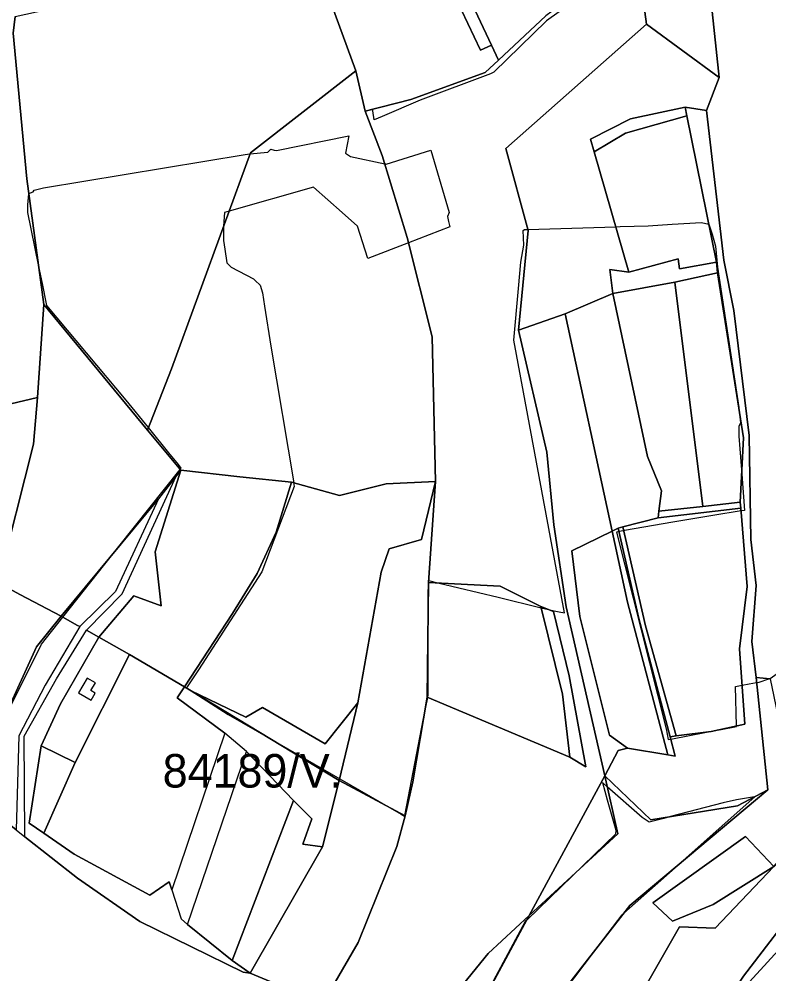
# Model space of a CAD drawing. Extents: x -477304 to -465429, y -1159113 to -1149210.
# Drawn here: x -472117.1 to -471781.8, y -1154340.7 to -1153913.5 of the extents above; entities that cross this region are included whole.
import ezdxf

# ---------------------------------------------------------------- set-up
doc = ezdxf.new("R2010")
doc.units = 0
for name, color, linetype in [('BPEJ_s', 7, 'Continuous'), ('PUPFL_s', 7, 'Continuous'), ('trav_porost_s', 7, 'Continuous'), ('zahrada_s', 7, 'Continuous')]:
    doc.layers.add(name, color=color, linetype=linetype)

msp = doc.modelspace()

# ---------------------------------------------------------------- linework, layer by layer
at = {"layer": 'BPEJ_s'}
for points in [[(-471858.64, -1153897.99), (-471881.28, -1153914.36), (-471904.87, -1153937.31), (-471906.36, -1153937.95), (-471937.82, -1153949.85), (-471954.82, -1153957.08), (-471958.28, -1153958.55), (-471958.86, -1153954.53), (-471958.96, -1153953.79), (-471962.4, -1153954.64), (-471966.51, -1153936.68), (-471979.78, -1153900.24)], [(-471858.64, -1153897.99), (-471881.28, -1153914.36), (-471904.87, -1153937.31), (-471906.36, -1153937.95), (-471937.82, -1153949.85), (-471954.82, -1153957.08), (-471958.28, -1153958.55), (-471958.86, -1153954.53), (-471958.96, -1153953.79), (-471962.4, -1153954.64), (-471966.51, -1153936.68), (-471979.78, -1153900.24)], [(-472126.75, -1154232.46), (-472107.09, -1154193.16), (-472097.54, -1154181.12), (-472072.46, -1154149.52), (-472045.06, -1154114.98), (-472044.62, -1154114.42), (-472045.9, -1154112.84), (-472050.19, -1154107.53), (-472059.27, -1154096.3), (-472069.27, -1154083.94), (-472104.75, -1154041.66), (-472106.75, -1154031.87), (-472108.45, -1154023.53), (-472113.24, -1154000), (-472113.17, -1153996.61), (-472112.76, -1153991.72), (-472112.76, -1153991.63), (-472112.75, -1153991.51), (-472110.83, -1153990.87), (-472110.41, -1153990.02), (-472106.16, -1153988.96), (-472016.03, -1153974.08), (-472013.9, -1153973.86), (-472005.83, -1153973.02), (-472004.56, -1153971.75), (-472003.05, -1153972.12), (-472002.01, -1153972.38), (-471969.66, -1153965.71), (-471971.18, -1153973.45), (-471968.85, -1153974.93), (-471953.61, -1153978.21), (-471953.3, -1153978.28), (-471952.9, -1153978.37), (-471932.93, -1153972.14), (-471924.85, -1154000), (-471925.54, -1154001.87), (-471925.04, -1154004), (-471924.46, -1154006.51), (-471942.98, -1154013.65), (-471961.11, -1154020.64), (-471965.76, -1154006.16), (-471972.63, -1154000), (-471985.42, -1153988.71), (-472023.22, -1153999.4), (-472025.33, -1154000), (-472025.71, -1154006.2), (-472025.71, -1154012.55), (-472025.13, -1154016.5), (-472024.23, -1154022.54), (-472022.31, -1154024.45), (-472012.33, -1154029.76), (-472011.53, -1154030.5), (-472009.35, -1154032.52), (-472008.29, -1154035.92), (-472007.33, -1154042), (-472004.52, -1154059.81), (-471994.33, -1154120.97), (-471994.21, -1154121.69), (-471994.05, -1154122.61), (-472008.5, -1154160.86), (-472036.97, -1154204.63), (-472042.28, -1154212.78), (-472023.59, -1154224.6), (-472004.72, -1154235.49), (-471973.74, -1154253.36), (-471951.23, -1154266.35), (-471946.24, -1154269.22), (-471944.69, -1154270.12), (-471944.65, -1154269.9), (-471936.21, -1154226.36), (-471934.38, -1154216.96), (-471934.13, -1154215.68), (-471934.13, -1154179.18), (-471934.13, -1154169.78), (-471933.99, -1154167.43), (-471933.88, -1154165.62), (-471933.83, -1154164.76), (-471929.29, -1154165.85)], [(-472069.27, -1154083.94), (-472104.75, -1154041.66), (-472106.75, -1154031.87), (-472108.45, -1154023.53), (-472113.24, -1154000), (-472113.17, -1153996.61), (-472112.76, -1153991.72), (-472112.76, -1153991.63), (-472112.75, -1153991.51), (-472110.83, -1153990.87), (-472110.41, -1153990.02), (-472106.16, -1153988.96), (-472016.03, -1153974.08), (-472013.9, -1153973.86), (-472005.83, -1153973.02), (-472004.56, -1153971.75), (-472003.05, -1153972.12), (-472002.01, -1153972.38), (-471969.66, -1153965.71), (-471971.18, -1153973.45), (-471968.85, -1153974.93), (-471953.61, -1153978.21), (-471953.3, -1153978.28), (-471952.9, -1153978.37), (-471932.93, -1153972.14), (-471924.85, -1154000), (-471925.54, -1154001.87), (-471925.04, -1154004), (-471924.46, -1154006.51), (-471942.98, -1154013.65), (-471961.11, -1154020.64), (-471965.76, -1154006.16), (-471972.63, -1154000), (-471985.42, -1153988.71), (-472023.22, -1153999.4), (-472025.33, -1154000), (-472025.71, -1154006.2), (-472025.71, -1154012.55), (-472025.13, -1154016.5), (-472024.23, -1154022.54), (-472022.31, -1154024.45), (-472012.33, -1154029.76), (-472011.53, -1154030.5), (-472009.35, -1154032.52), (-472008.29, -1154035.92), (-472007.33, -1154042), (-472004.52, -1154059.81), (-471994.33, -1154120.97), (-471994.21, -1154121.69), (-471994.05, -1154122.61), (-472008.5, -1154160.86), (-472036.97, -1154204.63), (-472042.28, -1154212.78), (-472023.59, -1154224.6), (-472004.72, -1154235.49), (-471973.74, -1154253.36), (-471951.23, -1154266.35), (-471946.24, -1154269.22), (-471944.69, -1154270.12), (-471944.65, -1154269.9), (-471936.21, -1154226.36), (-471934.38, -1154216.96), (-471934.13, -1154215.68), (-471934.13, -1154179.18), (-471934.13, -1154169.78), (-471933.99, -1154167.43), (-471933.88, -1154165.62), (-471933.83, -1154164.76), (-471929.29, -1154165.85), (-471902.91, -1154172.17), (-471883.62, -1154176.87), (-471880.4, -1154177.66), (-471877.83, -1154178.28), (-471875.63, -1154178.71), (-471873.17, -1154179.2), (-471895.89, -1154057.17), (-471893.77, -1154034.06), (-471892.7, -1154022.32), (-471891.42, -1154014.67), (-471891.64, -1154008.09), (-471891.01, -1154007.66), (-471889.53, -1154007.62), (-471850.27, -1154006.41), (-471848.31, -1154006.35), (-471835.76, -1154005.96), (-471825.02, -1154005.29), (-471811.96, -1154004.48), (-471808.65, -1154005.3), (-471808.56, -1154005.33), (-471807.2, -1154009.78), (-471805.58, -1154015.1), (-471804.73, -1154024.45), (-471795.17, -1154087.34), (-471795.15, -1154087.58), (-471794.53, -1154094.14), (-471795.17, -1154095.84), (-471795.17, -1154100.09), (-471793.92, -1154117.15), (-471792.74, -1154133.3), (-471794.21, -1154133.54), (-471806.89, -1154135.59)], [(-471929.29, -1154165.85), (-471902.91, -1154172.17), (-471883.62, -1154176.87), (-471880.4, -1154177.66), (-471877.83, -1154178.28), (-471875.63, -1154178.71), (-471873.17, -1154179.2), (-471895.89, -1154057.17), (-471893.77, -1154034.06), (-471892.7, -1154022.32), (-471891.42, -1154014.67), (-471891.64, -1154008.09), (-471891.01, -1154007.66), (-471889.53, -1154007.62), (-471850.27, -1154006.41), (-471848.31, -1154006.35), (-471835.76, -1154005.96), (-471825.02, -1154005.29), (-471811.96, -1154004.48), (-471808.65, -1154005.3), (-471808.56, -1154005.33), (-471807.2, -1154009.78), (-471805.58, -1154015.1), (-471804.73, -1154024.45), (-471795.17, -1154087.34), (-471795.15, -1154087.58), (-471794.53, -1154094.14), (-471795.17, -1154095.84), (-471795.17, -1154100.09), (-471793.92, -1154117.15), (-471792.74, -1154133.3), (-471794.21, -1154133.54), (-471806.89, -1154135.59), (-471824.79, -1154138.66), (-471846.38, -1154142.37), (-471846.55, -1154142.4), (-471846.73, -1154142.44), (-471848.84, -1154142.8), (-471850, -1154143), (-471827.68, -1154230.98), (-471826.86, -1154235.85), (-471825.69, -1154235.63), (-471809.62, -1154232.54), (-471806.51, -1154231.95), (-471803.07, -1154231.29), (-471796.19, -1154229.97), (-471796.2, -1154229.76), (-471796.68, -1154212.06), (-471793.77, -1154211.54), (-471790.64, -1154210.98), (-471787.26, -1154210.37), (-471786.04, -1154210.15), (-471781.79, -1154208.67), (-471781.7, -1154208.61)], [(-472126.75, -1154232.46), (-472107.09, -1154193.16), (-472097.54, -1154181.12), (-472072.46, -1154149.52), (-472045.06, -1154114.98), (-472044.62, -1154114.42), (-472045.9, -1154112.84), (-472050.19, -1154107.53), (-472059.27, -1154096.3), (-472069.27, -1154083.94)], [(-471806.89, -1154135.59), (-471824.79, -1154138.66), (-471846.38, -1154142.37), (-471846.55, -1154142.4), (-471846.73, -1154142.44), (-471848.84, -1154142.8), (-471850, -1154143), (-471827.68, -1154230.98), (-471826.86, -1154235.85), (-471825.69, -1154235.63), (-471809.62, -1154232.54), (-471806.51, -1154231.95), (-471803.07, -1154231.29), (-471796.19, -1154229.97), (-471796.2, -1154229.76), (-471796.68, -1154212.06), (-471793.77, -1154211.54), (-471790.64, -1154210.98), (-471787.26, -1154210.37), (-471786.04, -1154210.15), (-471781.79, -1154208.67), (-471781.7, -1154208.61)], [(-471912.04, -1154399.69), (-471855.58, -1154325.03), (-471847.44, -1154314.27), (-471846.65, -1154313.57), (-471821.16, -1154290.97), (-471820.19, -1154290.11), (-471787.83, -1154261.35), (-471788.13, -1154261.41), (-471796.24, -1154262.85), (-471802.18, -1154264.12), (-471825.76, -1154270.32), (-471828.78, -1154271.12), (-471835.33, -1154272.84), (-471838.52, -1154270.71), (-471854.05, -1154257.02), (-471856.2, -1154255.13), (-471854.03, -1154262.85), (-471850.2, -1154276.45), (-471850.42, -1154278.15), (-471869.64, -1154296.77), (-471889.96, -1154316.44), (-471890.79, -1154317.24), (-471935.82, -1154401.22)], [(-471912.04, -1154399.69), (-471855.58, -1154325.03), (-471847.44, -1154314.27), (-471846.65, -1154313.57), (-471821.16, -1154290.97), (-471820.19, -1154290.11), (-471787.83, -1154261.35), (-471788.13, -1154261.41), (-471796.24, -1154262.85), (-471802.18, -1154264.12), (-471825.76, -1154270.32), (-471828.78, -1154271.12), (-471835.33, -1154272.84), (-471838.52, -1154270.71), (-471854.05, -1154257.02), (-471856.2, -1154255.13), (-471854.03, -1154262.85), (-471850.2, -1154276.45), (-471850.42, -1154278.15), (-471869.64, -1154296.77), (-471889.96, -1154316.44), (-471890.79, -1154317.24), (-471935.82, -1154401.22)]]:
    msp.add_lwpolyline(points, dxfattribs=at)
at = {"layer": 'PUPFL_s'}
for points in [[(-471841.61, -1153878.07), (-471836.46, -1153915.86), (-471899.42, -1153971.4), (-471889.38, -1154008.16), (-471893.74, -1154052.75), (-471881.11, -1154107.33), (-471877.89, -1154139.79), (-471872.5, -1154176.44), (-471855.2, -1154252.01), (-471888.96, -1154314.59), (-471907.31, -1154331.52), (-471955.98, -1154391.34)], [(-471809.55, -1153887.46), (-471803.96, -1153939.59), (-471836.46, -1153915.86), (-471841.61, -1153878.07)], [(-471734.4, -1153905.75), (-471726.4, -1153959.93), (-471710.55, -1154003.53), (-471701.77, -1154028.61), (-471695.67, -1154044.05), (-471690.13, -1154061.98), (-471696.38, -1154070.81), (-471710.32, -1154086.43), (-471737.71, -1154129.54), (-471723.95, -1154151.12), (-471712.78, -1154176.98), (-471754.14, -1154191.03), (-471771.35, -1154201.7), (-471781.26, -1154208.65), (-471787.5, -1154208.08), (-471789.38, -1154191.93), (-471787.42, -1154166.99), (-471789.78, -1154146.28), (-471790.63, -1154099.78), (-471797.5, -1154043.85), (-471801.99, -1154021.33), (-471809.71, -1153954.36), (-471803.96, -1153939.59), (-471809.55, -1153887.46)], [(-472118.97, -1153912.3), (-472119.87, -1153919.78), (-472113.67, -1153985.03), (-472106.04, -1154041.27), (-472108.95, -1154082.78), (-472129.86, -1154087.81), (-472136.92, -1154051.38), (-472147.07, -1154009), (-472146.25, -1153978.67), (-472156.34, -1153957.61), (-472152.92, -1153942.04), (-472154.92, -1153925.34), (-472163.81, -1153915.07), (-472155.6, -1153912.17)], [(-471981.07, -1154353.65), (-471965.54, -1154326.58), (-471948.2, -1154283.67), (-471944.42, -1154270.02), (-471941.04, -1154254.76), (-471934.59, -1154216.87), (-471870.83, -1154243.66), (-471863.68, -1154248.06), (-471871.04, -1154207.41), (-471878.08, -1154178.62), (-471883.77, -1154176.26), (-471901.98, -1154167.18), (-471933.97, -1154165.62), (-471930.91, -1154120.34), (-471932.43, -1154055.71), (-471943.58, -1154011.28), (-471954.71, -1153974.57), (-471962.4, -1153954.64), (-471941.9, -1153949.55), (-471908.66, -1153937.46), (-471902.71, -1153931.9), (-471881.47, -1153912.02)], [(-472129.86, -1154087.81), (-472108.95, -1154082.78), (-472110.64, -1154103.7), (-472126.56, -1154165.78)], [(-471578.76, -1154463.85), (-471583.86, -1154490.96), (-471670.21, -1154492.33), (-471695.35, -1154463.3), (-471659.44, -1154426.99), (-471716.96, -1154340.3), (-471781.56, -1154355.08), (-471818.22, -1154378.77), (-471793.13, -1154341.75), (-471766.09, -1154306.48), (-471741.12, -1154276.97), (-471668.47, -1154252.77), (-471645.63, -1154265.51), (-471636.59, -1154269.05), (-471626.65, -1154273.16), (-471608.33, -1154269.66), (-471583.68, -1154248.83), (-471581.21, -1154243.16), (-471580.06, -1154226.43)]]:
    msp.add_lwpolyline(points, dxfattribs=at)
for points in [[(-472033.56, -1153904.42), (-472003.39, -1153894.1), (-471986.27, -1153882.43), (-471979.78, -1153900.24), (-471966.51, -1153936.68), (-472013.69, -1153973.29), (-472049, -1154070.03), (-472059.7, -1154097.39), (-472106.04, -1154041.27), (-472113.67, -1153985.03), (-472119.87, -1153919.78), (-472118.97, -1153912.3), (-472104.61, -1153909.28), (-472069.45, -1153902.97), (-472065.82, -1153902.95), (-472062.72, -1153902.93), (-472062.48, -1153907.01)], [(-471893.74, -1154052.75), (-471889.38, -1154008.16), (-471899.42, -1153971.4), (-471836.46, -1153915.86), (-471803.96, -1153939.59), (-471809.71, -1153954.36), (-471819.22, -1153952.9), (-471843.66, -1153958.17), (-471861.6, -1153967.31), (-471859.96, -1153972.97), (-471844.37, -1154026.79), (-471852.88, -1154025.58), (-471851.54, -1154036.22), (-471872.92, -1154045.39)], [(-471966.51, -1153936.68), (-471962.4, -1153954.64), (-471954.71, -1153974.57), (-471943.58, -1154011.28), (-471932.43, -1154055.71), (-471930.91, -1154120.34), (-471952.91, -1154121.48), (-471973.86, -1154126.7), (-471995.3, -1154120.7), (-472018.39, -1154118.27), (-472044.74, -1154115.37), (-472059.7, -1154097.39), (-472049, -1154070.03), (-472013.69, -1153973.29)], [(-471819.22, -1153952.9), (-471818.43, -1153956.82), (-471845.96, -1153964.51), (-471859.96, -1153972.97), (-471861.6, -1153967.31), (-471843.66, -1153958.17)], [(-471849.15, -1154240.79), (-471844.95, -1154239.68), (-471827.01, -1154242.67), (-471823.69, -1154243.22), (-471825.96, -1154234.59), (-471823.27, -1154234.25), (-471807.59, -1154232.29), (-471792.55, -1154228.95), (-471794.9, -1154195.31), (-471791.45, -1154167.34), (-471794.31, -1154132.34), (-471794.58, -1154129.64), (-471793.06, -1154100.8), (-471804.72, -1154027.04), (-471805.25, -1154022.24), (-471818.43, -1153956.82), (-471819.22, -1153952.9), (-471809.71, -1153954.36), (-471801.99, -1154021.33), (-471797.5, -1154043.85), (-471790.63, -1154099.78), (-471789.78, -1154146.28), (-471787.42, -1154166.99), (-471789.38, -1154191.93), (-471787.5, -1154208.08), (-471782.26, -1154258.3), (-471795.82, -1154265.47), (-471834.64, -1154271.76), (-471855.2, -1154252.01)], [(-471859.96, -1153972.97), (-471845.96, -1153964.51), (-471818.43, -1153956.82), (-471805.25, -1154022.24), (-471821.76, -1154025.21), (-471822.4, -1154020.77), (-471844.37, -1154026.79)], [(-471822.4, -1154020.77), (-471821.76, -1154025.21), (-471805.25, -1154022.24), (-471804.72, -1154027.04), (-471823.88, -1154031.15), (-471851.54, -1154036.22), (-471852.88, -1154025.58), (-471844.37, -1154026.79)], [(-471794.58, -1154129.64), (-471811.3, -1154131.55), (-471823.88, -1154031.15), (-471804.72, -1154027.04), (-471793.06, -1154100.8)], [(-471829.79, -1154124.58), (-471836.02, -1154109.24), (-471851.54, -1154036.22), (-471823.88, -1154031.15), (-471811.3, -1154131.55), (-471830.97, -1154133.67)], [(-471849.19, -1154141.26), (-471851.92, -1154142.59), (-471872.92, -1154045.39), (-471851.54, -1154036.22), (-471836.02, -1154109.24), (-471829.79, -1154124.58), (-471830.97, -1154133.67), (-471831.36, -1154136.63), (-471847.13, -1154140.72)], [(-472110.64, -1154103.7), (-472108.95, -1154082.78), (-472106.04, -1154041.27), (-472059.7, -1154097.39), (-472044.74, -1154115.37), (-472046.86, -1154118.07), (-472054.75, -1154128.13), (-472098.29, -1154180.7), (-472116.8, -1154170.98), (-472126.56, -1154165.78)], [(-471872.92, -1154045.39), (-471851.92, -1154142.59), (-471869.94, -1154151.37), (-471866.4, -1154180.86), (-471853.02, -1154233.87), (-471844.95, -1154239.68), (-471849.15, -1154240.79), (-471855.2, -1154252.01), (-471872.5, -1154176.44), (-471877.89, -1154139.79), (-471881.11, -1154107.33), (-471893.74, -1154052.75)], [(-472046.86, -1154118.07), (-472044.74, -1154115.37), (-472056.25, -1154151.79), (-472053.58, -1154176.08), (-472065.78, -1154171.6), (-472081.46, -1154190.05), (-472087, -1154186.98), (-472071.02, -1154170.63)], [(-472056.25, -1154151.79), (-472044.74, -1154115.37), (-472018.39, -1154118.27), (-471995.3, -1154120.7), (-472002.21, -1154143.01), (-472010.67, -1154161.59), (-472021.72, -1154179.43), (-472043.18, -1154212.24), (-472067.79, -1154197.85), (-472081.46, -1154190.05), (-472065.78, -1154171.6), (-472053.58, -1154176.08)], [(-472008.33, -1154221.51), (-472015.8, -1154225.83), (-472040.23, -1154214.01), (-472043.18, -1154212.24), (-472021.72, -1154179.43), (-472010.67, -1154161.59), (-472002.21, -1154143.01), (-471995.3, -1154120.7), (-471973.86, -1154126.7), (-471952.91, -1154121.48), (-471930.91, -1154120.34), (-471937.18, -1154146.38), (-471951.64, -1154150.57), (-471955.25, -1154160.89), (-471965.64, -1154219.46), (-471980.19, -1154237.83)], [(-471934.59, -1154216.87), (-471941.04, -1154254.76), (-471944.42, -1154270.02), (-471973.92, -1154254.12), (-471965.64, -1154219.46), (-471955.25, -1154160.89), (-471951.64, -1154150.57), (-471937.18, -1154146.38), (-471930.91, -1154120.34), (-471933.97, -1154165.62)], [(-472089.95, -1154185.34), (-472091.31, -1154184.6), (-472098.29, -1154180.7), (-472054.75, -1154128.13), (-472074.01, -1154169.64)], [(-471836.89, -1154184.99), (-471847.13, -1154140.72), (-471831.36, -1154136.63), (-471794.31, -1154132.34), (-471791.45, -1154167.34), (-471794.9, -1154195.31), (-471792.55, -1154228.95), (-471807.59, -1154232.29), (-471823.27, -1154234.25)], [(-471811.3, -1154131.55), (-471794.58, -1154129.64), (-471794.31, -1154132.34), (-471831.36, -1154136.63), (-471830.97, -1154133.67)], [(-471844.94, -1154174.41), (-471851.92, -1154142.59), (-471849.19, -1154141.26), (-471839.88, -1154181.67), (-471825.96, -1154234.59), (-471823.69, -1154243.22), (-471827.01, -1154242.67)], [(-471823.27, -1154234.25), (-471825.96, -1154234.59), (-471839.88, -1154181.67), (-471849.19, -1154141.26), (-471847.13, -1154140.72), (-471836.89, -1154184.99)], [(-471853.02, -1154233.87), (-471866.4, -1154180.86), (-471869.94, -1154151.37), (-471851.92, -1154142.59), (-471844.94, -1154174.41), (-471827.01, -1154242.67), (-471844.95, -1154239.68)], [(-472109.32, -1154194.4), (-472138.87, -1154258.95), (-472149, -1154248.98), (-472154.71, -1154243.06), (-472143.77, -1154210.95), (-472131.9, -1154185.3), (-472126.56, -1154165.78), (-472116.8, -1154170.98), (-472098.29, -1154180.7)], [(-471870.83, -1154243.66), (-471934.59, -1154216.87), (-471933.97, -1154165.62), (-471901.98, -1154167.18), (-471883.77, -1154176.26), (-471874.08, -1154215.47)], [(-471870.83, -1154243.66), (-471874.08, -1154215.47), (-471883.77, -1154176.26), (-471878.08, -1154178.62), (-471871.04, -1154207.41), (-471863.68, -1154248.06)], [(-472109.32, -1154194.4), (-472098.29, -1154180.7), (-472091.31, -1154184.6), (-472089.95, -1154185.34), (-472105.56, -1154211.52), (-472117.31, -1154234.13), (-472118.45, -1154276.25), (-472134.66, -1154263.23), (-472138.87, -1154258.95)], [(-471837.82, -1154347.78), (-471848.06, -1154350.73), (-471868.97, -1154369.01), (-471884.48, -1154408.39), (-471914.29, -1154400.4), (-471843.95, -1154310.1), (-471782.26, -1154258.3), (-471787.5, -1154208.08), (-471781.26, -1154208.65), (-471772.05, -1154252.6), (-471770.57, -1154253.93), (-471748.55, -1154273.72), (-471763.47, -1154290.85), (-471771.93, -1154283.95), (-471779.56, -1154292.63), (-471792.26, -1154279.16), (-471833.62, -1154308.86), (-471824.85, -1154317.17), (-471806.7, -1154309.59), (-471779.56, -1154292.63), (-471805.86, -1154320.16), (-471821.72, -1154319.63)], [(-471981.43, -1154283.83), (-471990.23, -1154282.68), (-471986.24, -1154271.38), (-471994.42, -1154263.08), (-472015.45, -1154241.12), (-472025.1, -1154232.95), (-472046.46, -1154217.13), (-472043.18, -1154212.24), (-472040.23, -1154214.01), (-471973.92, -1154254.12)], [(-471980.19, -1154237.83), (-471965.64, -1154219.46), (-471973.92, -1154254.12), (-472040.23, -1154214.01), (-472015.8, -1154225.83), (-472008.33, -1154221.51)], [(-471782.26, -1154258.3), (-471843.95, -1154310.1), (-471914.29, -1154400.4), (-471926.3, -1154475.13), (-471961.55, -1154462.05), (-471957.95, -1154398.09), (-471935.7, -1154401.24), (-471888.96, -1154314.59), (-471849.26, -1154277.96), (-471855.2, -1154252.01), (-471834.64, -1154271.76), (-471795.82, -1154265.47)], [(-471855.2, -1154252.01), (-471849.26, -1154277.96), (-471888.96, -1154314.59)], [(-471981.43, -1154283.83), (-471973.92, -1154254.12), (-471944.42, -1154270.02), (-471948.2, -1154283.67), (-471965.54, -1154326.58), (-471981.07, -1154353.65), (-471985.85, -1154352.04), (-472013.74, -1154340.31)], [(-472118.45, -1154276.25), (-472114.63, -1154279.3), (-472091, -1154297.81), (-472063.16, -1154317.31), (-472016.85, -1154339.92), (-472013.74, -1154340.31), (-471985.85, -1154352.04), (-471981.07, -1154353.65), (-472002.86, -1154394.15), (-472050.95, -1154379.38), (-472068.05, -1154373.16), (-472106.23, -1154357.73), (-472143.62, -1154354.24), (-472181.45, -1154349.57), (-472138.87, -1154258.95), (-472134.66, -1154263.23)], [(-471986.24, -1154271.38), (-471990.23, -1154282.68), (-471981.43, -1154283.83), (-472013.74, -1154340.31), (-472021.8, -1154334.74), (-471994.42, -1154263.08)], [(-471674.79, -1154269.38), (-471718.59, -1154289.97), (-471745.29, -1154324.08), (-471721.3, -1154284.54), (-471726.92, -1154281.54), (-471746.93, -1154296.63), (-471790.43, -1154344.3), (-471785.46, -1154348.33), (-471763.4, -1154337.64), (-471712.96, -1154324.74)], [(-471745.29, -1154324.08), (-471718.59, -1154289.97), (-471674.79, -1154269.38), (-471712.96, -1154324.74), (-471763.4, -1154337.64), (-471785.46, -1154348.33), (-471790.43, -1154344.3), (-471746.93, -1154296.63), (-471726.92, -1154281.54), (-471721.3, -1154284.54)], [(-471821.72, -1154319.63), (-471805.86, -1154320.16), (-471779.56, -1154292.63), (-471771.93, -1154283.95), (-471763.47, -1154290.85), (-471748.55, -1154273.72), (-471741.12, -1154276.97), (-471766.09, -1154306.48), (-471793.13, -1154341.75), (-471818.22, -1154378.77), (-471837.2, -1154392.79), (-471884.48, -1154408.39), (-471868.97, -1154369.01), (-471848.06, -1154350.73), (-471837.82, -1154347.78)], [(-471833.62, -1154308.86), (-471792.26, -1154279.16), (-471779.56, -1154292.63), (-471806.7, -1154309.59), (-471824.85, -1154317.17)], [(-471955.98, -1154391.34), (-471907.31, -1154331.52), (-471888.96, -1154314.59), (-471935.7, -1154401.24), (-471957.95, -1154398.09)]]:
    msp.add_lwpolyline(points, close=True, dxfattribs=at)
at = {"layer": 'trav_porost_s'}
for points in [[(-471932.86, -1153867.76), (-471939.93, -1153850.17), (-471953.6, -1153816.18), (-471956.97, -1153797.64), (-471965.11, -1153762.38), (-471951.67, -1153747.01), (-471940.5, -1153740.47), (-471928.71, -1153737.8), (-471924.15, -1153737.15), (-471912.4, -1153768.87), (-471903.08, -1153785.48), (-471890.27, -1153820.51), (-471861.67, -1153897.31), (-471881.47, -1153912.02), (-471902.71, -1153931.9), (-471905.84, -1153925.24)], [(-471944.54, -1153873.02), (-471935.52, -1153868.91), (-471932.86, -1153867.76), (-471905.84, -1153925.24), (-471910.8, -1153927.47), (-471933.36, -1153879.59), (-471961.42, -1153891.59), (-471979.78, -1153900.24), (-471986.27, -1153882.43), (-471976.82, -1153883.59), (-471973.01, -1153893.64), (-471951.44, -1153881.02)], [(-471962.4, -1153954.64), (-471966.51, -1153936.68), (-471979.78, -1153900.24), (-471961.42, -1153891.59), (-471933.36, -1153879.59), (-471910.8, -1153927.47), (-471905.84, -1153925.24), (-471902.71, -1153931.9), (-471908.66, -1153937.46), (-471941.9, -1153949.55)], [(-472050.03, -1154299.56), (-472048.8, -1154303.1), (-472044.67, -1154316.01), (-472041.82, -1154318.54), (-472021.8, -1154334.74), (-472013.74, -1154340.31), (-472016.85, -1154339.92), (-472063.16, -1154317.31), (-472091, -1154297.81), (-472114.63, -1154279.3), (-472114.93, -1154234.33), (-472100.47, -1154208.73), (-472087, -1154186.98), (-472081.46, -1154190.05), (-472098.64, -1154219.92), (-472107.31, -1154238.67), (-472112.7, -1154273.2), (-472106.08, -1154277.68), (-472092.54, -1154287.07), (-472058.73, -1154305.48)], [(-472067.79, -1154197.85), (-472043.18, -1154212.24), (-472046.46, -1154217.13), (-472025.1, -1154232.95), (-472048.8, -1154303.1), (-472050.03, -1154299.56), (-472058.73, -1154305.48), (-472092.54, -1154287.07), (-472106.08, -1154277.68), (-472092.02, -1154246.09)], [(-472107.31, -1154238.67), (-472092.02, -1154246.09), (-472106.08, -1154277.68), (-472112.7, -1154273.2)], [(-472015.45, -1154241.12), (-471994.42, -1154263.08), (-472021.8, -1154334.74), (-472041.82, -1154318.54)]]:
    msp.add_lwpolyline(points, close=True, dxfattribs=at)
at = {"layer": 'zahrada_s'}
for points in [[(-472098.64, -1154219.92), (-472081.46, -1154190.05), (-472067.79, -1154197.85), (-472092.02, -1154246.09), (-472107.31, -1154238.67)], [(-472090.58, -1154215.01), (-472084.94, -1154218.24), (-472083.1, -1154215.03), (-472085.01, -1154213.94), (-472083.02, -1154210.47), (-472086.75, -1154208.33)]]:
    msp.add_lwpolyline(points, close=True, dxfattribs=at)

# ---------------------------------------------------------------- texts
at = {"layer": 'BPEJ_s'}
msp.add_text('84189/V.', height=15, dxfattribs=at).set_placement((-472052.93, -1154257.32))

doc.saveas('drawing.dxf')
